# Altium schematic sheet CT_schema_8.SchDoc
size 372 x 245 mm
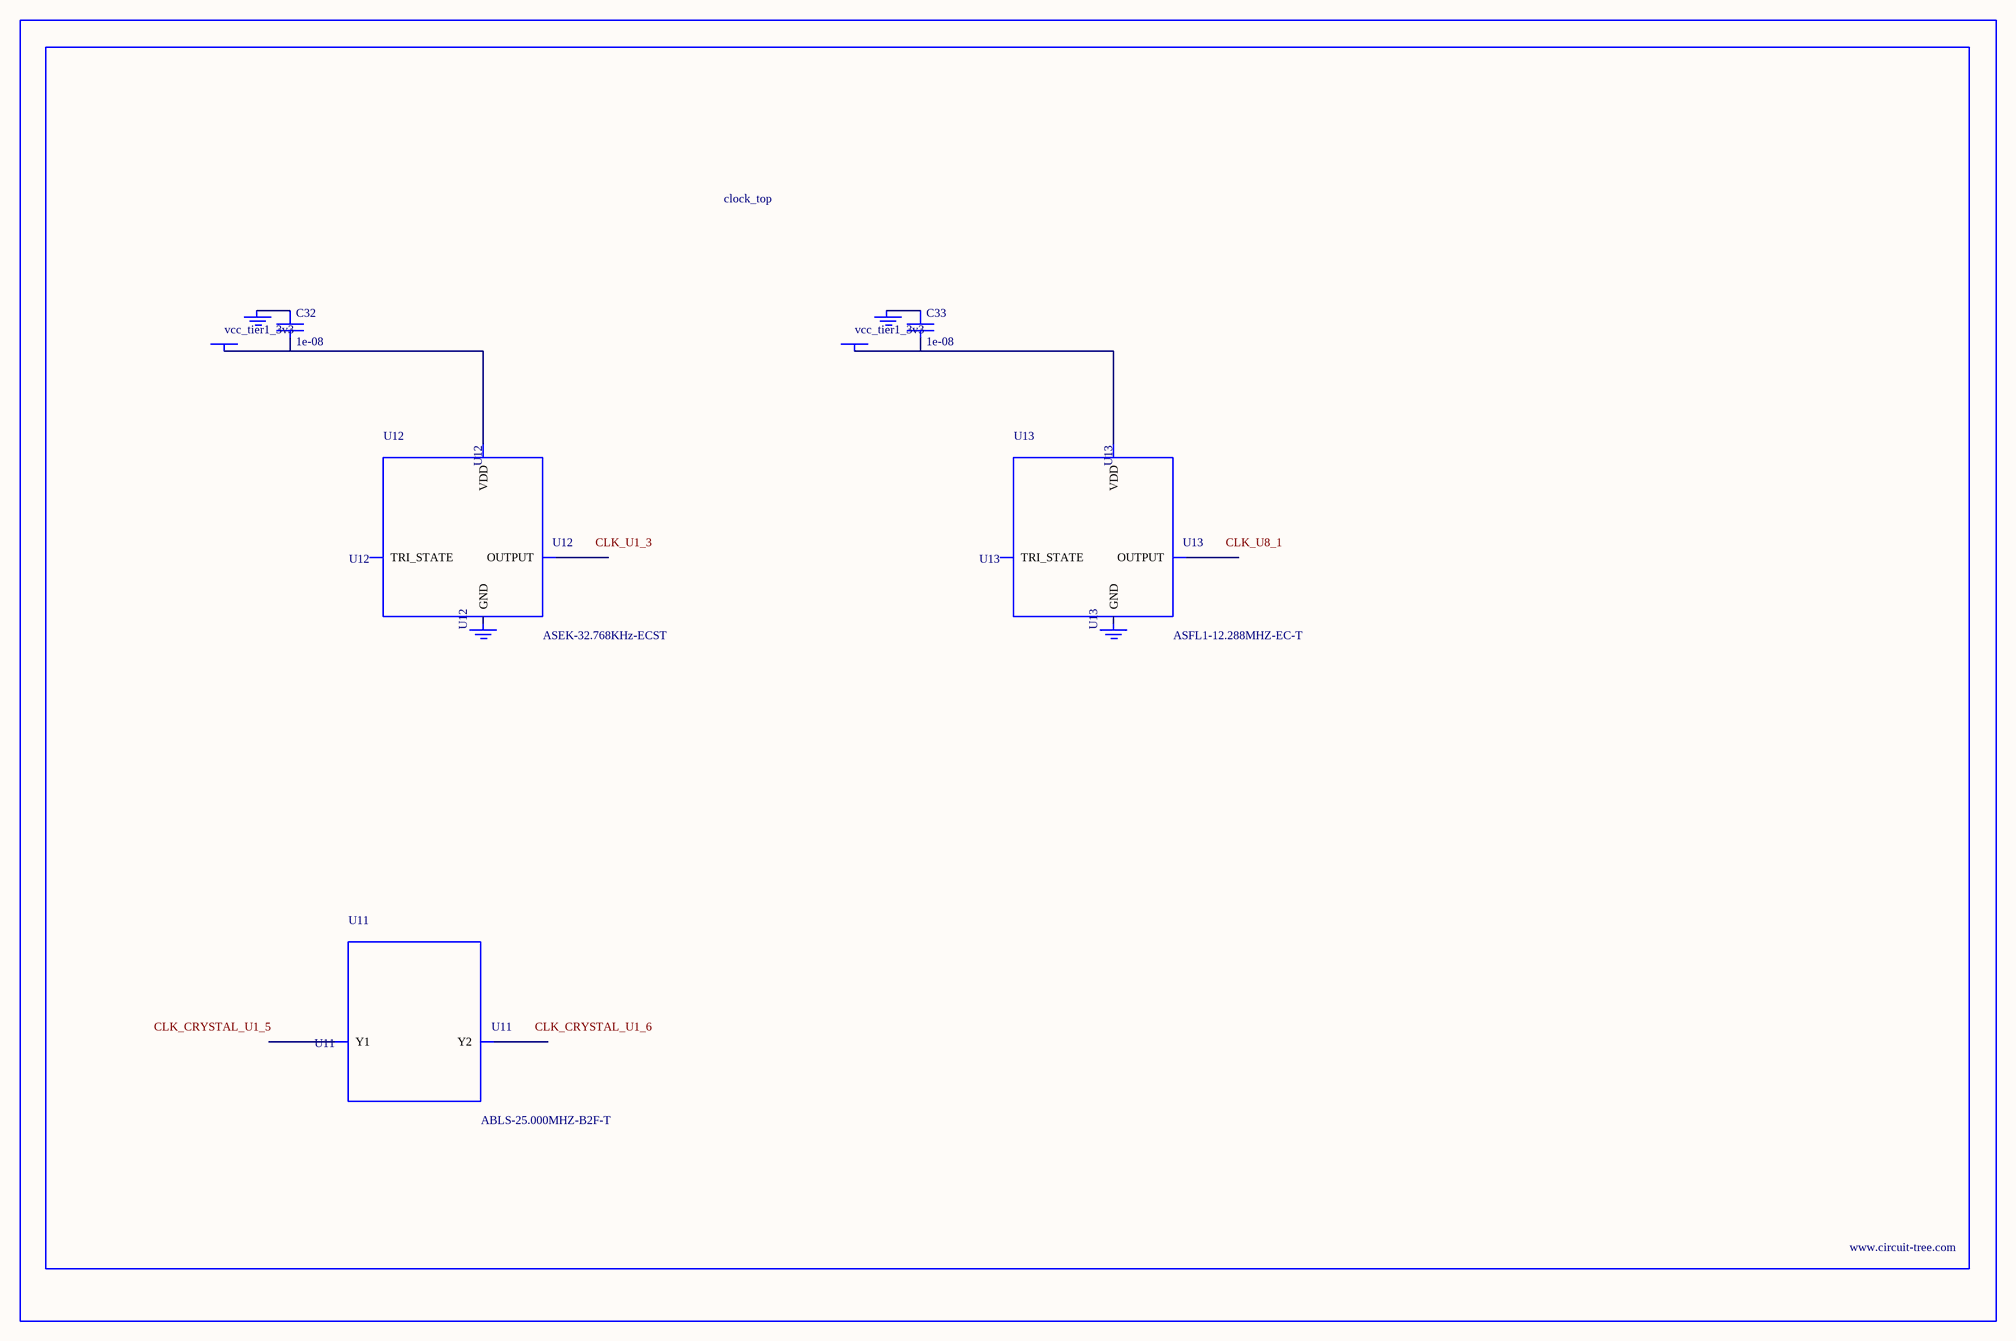
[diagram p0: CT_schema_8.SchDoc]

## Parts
BORDER7  (no value)
C32  1e-08  [C0402]
C33  1e-08  [C0402]
GND_INSTANCE_7_0  (no value)
GND_INSTANCE_7_1  (no value)
GND_INSTANCE_7_2  (no value)
GND_INSTANCE_7_3  (no value)
POWER_INSTANCE_7_0  vcc_tier1_3v3
POWER_INSTANCE_7_1  vcc_tier1_3v3
U11  ABLS-25.000MHZ-B2F-T  [ABLS-25.000MHZ-B2F-T]
U12  ASEK-32.768KHz-ECST  [ASEK]
U13  ASFL1-12.288MHZ-EC-T  [ASFL1]

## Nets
NetC32_1: C32.1 GND_INSTANCE_7_0.0(GND)
NetC32_2: C32.2 POWER_INSTANCE_7_0.0(PWR) U12.4(VDD)
NetC33_1: C33.1 GND_INSTANCE_7_2.0(GND)
NetC33_2: C33.2 POWER_INSTANCE_7_1.0(PWR) U13.4(VDD)

Not connected (* = marked no-connect by the designer): GND_INSTANCE_7_1 0(GND); GND_INSTANCE_7_3 0(GND); U11 1(Y1) 2(Y2); U12 1(TRI_STATE) 2(GND) 3(OUTPUT); U13 1(TRI_STATE) 2(GND) 3(OUTPUT)

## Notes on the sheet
- Labels drawn without touching a wire or pin: CLK_CRYSTAL_U1_5, CLK_CRYSTAL_U1_6, CLK_U1_3, CLK_U8_1

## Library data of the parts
BORDER7 = BORDER_PAGE7
C32 C33 = C0402C103K3RAC
GND_INSTANCE_7_0-GND_INSTANCE_7_3 = GND
POWER_INSTANCE_7_0 POWER_INSTANCE_7_1 = PWR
